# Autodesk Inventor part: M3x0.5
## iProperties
Created: 2009-02
Part Number: M3x0.5
Material: 강, 연강
Description: 6각머리 태핑 나사
Document SubType Name: Modeling
Standard: KS B 1003
Designer: 한국산업디자인학원-SeoGD™
Standards Organization: KS
Language: ko-KR
Size Designation: M 3 x 6
Categories: <MemberInstance><Categories><Category DisplayName="조임쇠" InternalName="e4da775c-781d-43d5-af7c-5136215cf5a6" Mnemonic="FSTN"><Category DisplayName="볼트" InternalN
Density: 7.86 g/cm^3
Mass: 0.818725 g
Surface Area: 1.64152 cm^2
Volume: 0.104163 cm^3
IsCustomPart: 1
Author: 진현석
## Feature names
1. Fillet2
